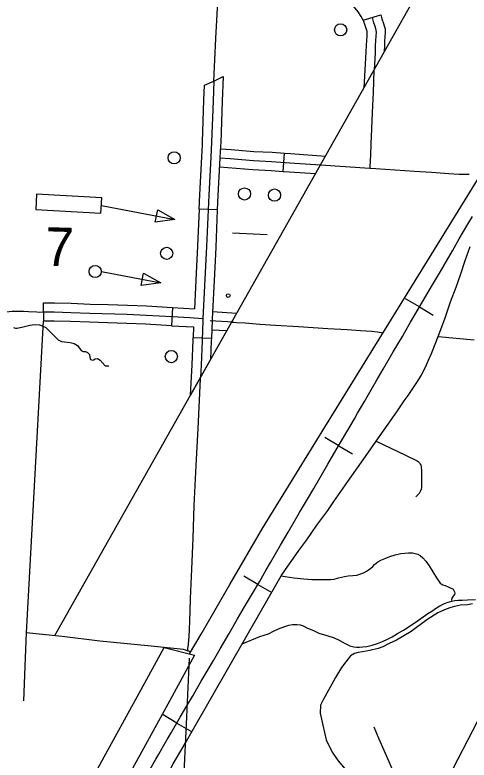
# Model space of a CAD drawing. Extents: x 653372 to 905732, y 627442 to 787275.
# Drawn here: x 693304 to 697040, y 749166 to 755293 of the extents above; entities that cross this region are included whole.
import ezdxf

# ---------------------------------------------------------------- set-up
doc = ezdxf.new("R2010")
doc.units = 0
for name, color, linetype in [('15', 7, 'Continuous'), ('31', 7, 'Continuous'), ('32', 7, 'Continuous'), ('33', 7, 'Continuous'), ('35', 7, 'Continuous'), ('40', 7, 'Continuous'), ('45', 7, 'Continuous'), ('46', 7, 'Continuous'), ('56', 7, 'Continuous'), ('57', 7, 'Continuous'), ('6', 7, 'Continuous'), ('63', 7, 'Continuous')]:
    doc.layers.add(name, color=color, linetype=linetype)

msp = doc.modelspace()

# ---------------------------------------------------------------- linework, layer by layer
at = {"layer": '15'}
for points in [[(694740.6, 750040.6), (694835.2, 750202.4), (695073.2, 750608.7), (695344.3, 751076.3), (695832.2, 751869.1), (697303.4, 754253.1)], [(693255.3, 747643), (693125.3, 747883.4), (693577.6, 748439.7), (693782.1, 748722.2), (693910, 748955), (694023, 749162.6), (694325.7, 749716.7), (694531.2, 750092.3), (694781, 750027.9)], [(694781, 750027.9), (694545.1, 749596.7), (694242.5, 749042.9), (694129.3, 748835), (693993.7, 748588.1), (693776.2, 748287.7), (693255.3, 747643)]]:
    msp.add_lwpolyline(points, dxfattribs=at)
at = {"layer": '31'}
for p, q in [((694969.2, 753689.8), (694819.4, 753696.4)), ((694819.4, 753696.4), (694819.4, 753696.4)), ((693540.9, 752775.5), (693540.1, 752925.5)), ((693540.1, 752925.5), (693540.1, 752925.5)), ((694600, 752887.4), (694591.4, 752737.6)), ((694770.5, 752641), (694920.4, 752635.4))]:
    msp.add_line(p, q, dxfattribs=at)
for points in [[(694941.2, 754748), (694957.2, 755099.5), (694985.9, 755652), (694986.9, 755707.5), (694990.1, 755812.4)], [(694941.2, 754748), (694933.9, 754587.5), (694922.4, 754246.4), (694915.8, 754122.6), (694899.5, 753811.1), (694880.9, 753387.8), (694851.3, 752796.2), (694850.8, 752782.5), (694844.6, 752615.9), (694836.5, 752412.3), (694831.2, 752313.7)], [(694846.1, 754224.3), (694847.4, 754249.6), (694859, 754590.5), (694864.6, 754714.4), (694941.2, 754748), (695018.1, 754787)], [(695018.1, 754787), (695008.9, 754584.5), (694997.3, 754243.1), (694995.9, 754216.4)], [(694819.4, 753696.4), (694824.6, 753814.7), (694840.9, 754126.6), (694846.1, 754224.3)], [(694995.9, 754216.4), (694990.7, 754118.7), (694974.4, 753807.4), (694969.2, 753689.8)], [(694819.4, 753696.4), (694805.9, 753391.3), (694794.9, 753169.4)], [(694969.2, 753689.8), (694955.8, 753384.3), (694944.7, 753161.9)], [(696786.7, 752647.6), (696839.7, 752792.8), (696887.2, 752932.4), (696934.1, 753054.5), (696968.6, 753154.7), (697009.1, 753272.9), (697048.8, 753387.6)], [(694794.9, 753169.4), (694780.3, 752877.5)], [(694944.7, 753161.9), (694926.2, 752792.8), (694925.7, 752779.7), (694920.4, 752635.4)], [(693540.1, 752925.5), (693556.4, 752925.6), (693629.4, 752926), (693768, 752921.8), (693922.2, 752915.7), (694070.5, 752911.3)], [(694070.5, 752911.3), (694229.2, 752906.5), (694387.6, 752899.6), (694600, 752887.4)], [(693540.5, 752850.5), (693556.8, 752850.6), (693628.4, 752851), (693765.4, 752846.8), (693919.6, 752840.8), (694226.4, 752831.6), (694383.8, 752824.6), (694596.6, 752812.5), (694742.1, 752804.5), (694851.3, 752796.2)], [(694600, 752887.4), (694600.9, 752887.3), (694780.3, 752877.5)], [(694066, 752761.3), (693917, 752765.8), (693762.8, 752771.9), (693627.5, 752776), (693557.2, 752775.6), (693540.9, 752775.5)], [(694591.4, 752737.6), (694380.1, 752749.7), (694223.6, 752756.6), (694066, 752761.3)], [(694591.4, 752737.6), (694592.4, 752737.6), (694773.7, 752727.6)], [(694773.7, 752727.6), (694770.5, 752641)], [(694748.3, 752166.9), (694761.6, 752415.8), (694769.6, 752618.8), (694770.5, 752641)], [(694920.4, 752635.4), (694919.5, 752613), (694913.4, 752459.2), (694748.3, 752166.9)], [(696274.7, 751788.2), (696373.6, 751927.5), (696450.9, 752038.3), (696505.1, 752121.2), (696537.8, 752164.4), (696583, 752230), (696610.1, 752271.1), (696629.1, 752299.9), (696648.2, 752330.7), (696663.7, 752361), (696681.4, 752395.9), (696706.8, 752453.1), (696731.5, 752508.2), (696761.1, 752586.9), (696786.7, 752647.6)], [(694725.8, 750070.8), (694727.2, 750081.2), (694731.2, 750116.8), (694736.5, 750184.4), (694739.7, 750236.9), (694743, 750314.5), (694745.1, 750394.4), (694749.1, 750494.3), (694758.6, 750735.9), (694769.9, 750991.2), (694779.9, 751259.3), (694794.1, 751588.9), (694810.4, 751892), (694830.5, 752299.5), (694831.2, 752313.7)], [(694705.6, 749303.5), (694773.5, 749422.8), (695493.5, 750682.4), (695549.6, 750760.3), (695594.8, 750826.6), (695640.7, 750888.8), (695705.4, 750977.6), (695787.2, 751098.7), (695877.4, 751217.5), (695927.1, 751292.8), (696044, 751456.4), (696187.7, 751662.9), (696274.7, 751788.2)], [(695173.6, 750122.7), (695319.3, 750181.6), (695391.5, 750204.4), (695432.4, 750226.3), (695473.7, 750246.7), (695525.6, 750264.1), (695557.8, 750274.5), (695587.8, 750280.1), (695622.5, 750282.3), (695651.6, 750277.7), (695676.2, 750269.3), (695711.2, 750252), (695759.3, 750232.1), (695804.7, 750210.7), (695870.2, 750191.5), (695930.2, 750172.3), (695972.4, 750153.2), (695996.3, 750139.5), (696020.1, 750125.8), (696044.1, 750113.7), (696060.6, 750106.1), (696091.7, 750097.1), (696113.3, 750093.7), (696137.7, 750094.1), (696163.2, 750096.6), (696198.5, 750101.5), (696243.7, 750110.9), (696287.7, 750125.9), (696328.2, 750142), (696368.8, 750159.7), (696406.2, 750179.7), (696450.8, 750206), (696502.1, 750235.8), (696546.8, 750264.8), (696624.7, 750317.7), (696701, 750372.2), (696732.5, 750391.3), (696771.7, 750418.8), (696800.9, 750435.8), (696837.1, 750452.6), (696868.4, 750465.2), (696898.4, 750473.5), (696922.3, 750477.6), (696951.1, 750481.6), (696984.4, 750482.2), (697027.3, 750484.2), (697093.4, 750486)]]:
    msp.add_lwpolyline(points, dxfattribs=at)
at = {"layer": '32'}
msp.add_line((695512, 754006.1), (695522.7, 754155.8), dxfattribs=at)
for points in [[(694995.6, 754192), (695081.9, 754185.6), (695270.9, 754170.3), (695420.6, 754163.1), (695522.7, 754155.8)], [(695522.7, 754155.8), (695571.4, 754152.3), (695858.2, 754132.2)], [(694990.7, 754117.1), (695076.1, 754110.9), (695266, 754095.5), (695416.1, 754088.2), (695566.1, 754077.5), (695817.4, 754059.9)], [(694986.8, 754042.9), (695261.2, 754020.6), (695411.6, 754013.3), (695512, 754006.1)], [(695512, 754006.1), (695560.8, 754002.6), (695776.6, 753987.5)], [(695817.3, 754059.6), (696224.4, 754033.4), (696272.5, 754029.2), (696592.4, 754008.5), (696730.1, 754000.3), (696873.8, 753989.7), (696957.4, 753983.7), (697021.1, 753983.2), (697040.5, 753982.6)], [(695128, 752839.2), (694929.2, 752851.9)], [(695100.1, 752765.8), (694909.8, 752778)], [(695087.1, 752766.7), (695127.4, 752764.1), (695198.7, 752761.4), (695319.9, 752750.6), (695447, 752743.2), (695637.9, 752729.7), (695879.7, 752715.9), (696038.6, 752706.9), (696146.2, 752698.3), (696240.6, 752691.3), (696285.7, 752687.6), (696331.2, 752677.7)], [(695046.1, 752694.1), (694922.8, 752702)], [(696786.7, 752647.6), (697083.1, 752622.2)], [(695493.5, 750682.4), (695528.6, 750676.2), (695597.6, 750665.5), (695681.2, 750657.6), (695746.6, 750651.3), (695780.1, 750650.3), (695821.8, 750650.1), (695872.1, 750650.2), (695900.5, 750651.5), (695929.8, 750655), (695966.4, 750663.6), (696016.5, 750675.6), (696045.9, 750680.7), (696083.9, 750685), (696115.9, 750687.8), (696133.4, 750691.1), (696159.1, 750700.1), (696177.7, 750707.6), (696201.4, 750722.1), (696231.9, 750745.5), (696247.4, 750757.5), (696263.3, 750774.4), (696288.3, 750795.3), (696315.3, 750810.7), (696355.3, 750827.4), (696388.2, 750839.9), (696432.4, 750852.7), (696479.3, 750863.7), (696512.4, 750868.7), (696541.7, 750871), (696574.2, 750869.5), (696597.3, 750864.5), (696618.1, 750859), (696636.7, 750848.7), (696659.9, 750829), (696684, 750802.3), (696711, 750763.6), (696773, 750663.7), (696803.1, 750620.6), (696810.5, 750614.4), (696824.3, 750607.5), (696842.5, 750601.5), (696867, 750591.1), (696908.1, 750570.3), (696915.4, 750561.5), (696921, 750551), (696921.8, 750540.1), (696919.8, 750528.8), (696908, 750512.9), (696898.9, 750498.6), (696895.2, 750484.1), (696898.4, 750473.5)]]:
    msp.add_lwpolyline(points, dxfattribs=at)
at = {"layer": '33'}
for points in [[(692906.9, 752853.4), (692973.4, 752852.4), (693013.2, 752851.8), (693094.2, 752849.7), (693156.7, 752849.8), (693211, 752852.9), (693256.5, 752855.5), (693281.3, 752857.1), (693309.6, 752857), (693346.5, 752856.7), (693375.2, 752855.9), (693414.8, 752854.3), (693483.9, 752850.6), (693508.6, 752849.9), (693540.5, 752850.5)], [(694749.5, 750055.9), (694691.9, 750075.8), (694398.3, 750105.9), (694004, 750145.1), (693691.7, 750181.8), (693397.5, 750213.1), (693388.9, 750006.8), (693374.1, 749654.1)], [(694723, 750062.7), (694725.8, 750070.8)], [(693300.2, 747217.8), (693538.5, 747527.5), (693619.8, 747634.1), (693710.8, 747747.8), (693807.8, 747869.9), (693900.6, 747992.3), (693950.9, 748063.4), (694025.6, 748169.8), (694104.2, 748284.2), (694138.4, 748345), (694210.2, 748462.9), (694313, 748628.2), (694349.3, 748688.3), (694397.1, 748770), (694430.5, 748825.4), (694478.5, 748910.6), (694530.8, 748998), (694606.2, 749134.9), (694705.6, 749303.5)]]:
    msp.add_lwpolyline(points, dxfattribs=at)
at = {"layer": '35'}
for points in [[(693291.4, 752722.5), (693310, 752716.2), (693319.4, 752716.8), (693361.4, 752726.2), (693426.6, 752742.8), (693465.7, 752748.7), (693505.5, 752745.8), (693528.3, 752737.1), (693558.9, 752722.9), (693623.4, 752657.1), (693661.3, 752621.4), (693687.5, 752606.4), (693759.9, 752599), (693791.6, 752591.8), (693820.4, 752575.9), (693848.5, 752533.5), (693866.8, 752524.1), (693884.6, 752526.2), (693901.2, 752518.6), (693916.6, 752499.5), (693919.5, 752478.1), (693927, 752460.2), (693944.5, 752454.3), (693950.4, 752457.5), (693964.3, 752464.4), (693984.8, 752467.3), (694006.6, 752455.1), (694047.7, 752407.8), (694077.4, 752406.9)], [(697068.6, 750451.7), (697026.2, 750442), (696968.6, 750439.9), (696920, 750428.9), (696883, 750417.5), (696838.5, 750402.4), (696783.2, 750376), (696693.5, 750318.8), (696563, 750224.6), (696442.6, 750153.4), (696383.3, 750124), (696331.9, 750096.8), (696292.6, 750083.9), (696225.1, 750066.5), (696162.5, 750055.1), (696127.3, 750050), (696098.2, 750041.5), (696065.7, 750023), (696027.7, 749975.1), (695990.5, 749928.7), (695966.8, 749885.2), (695942.3, 749845.5), (695838.8, 749662.3)], [(695838.8, 749662.3), (695818.9, 749617.3), (695815.4, 749552), (695837.4, 749453.2), (695864.9, 749334), (695913.3, 749232.9), (695962.4, 749159.7), (696049.7, 749059), (696107.2, 749004.3), (696153.5, 748938.4), (696238.8, 748822.2), (696278.4, 748741.6), (696306.9, 748653.5), (696330.7, 748564), (696354, 748458.9), (696363.2, 748351.2)]]:
    msp.add_lwpolyline(points, dxfattribs=at)
at = {"layer": '40'}
for p, q in [((696632.1, 752892), (696518.2, 752958.6)), ((696632.1, 752892), (696746.1, 752825.3)), ((695968.1, 751751.2), (695854.6, 751818.5)), ((695968.1, 751751.2), (696081.7, 751683.8)), ((695302.6, 750611.2), (695188.6, 750677.7)), ((695302.6, 750611.2), (695416.6, 750544.8)), ((694636.9, 749471.4), (694523.4, 749538.8)), ((694636.9, 749471.4), (694750.4, 749404))]:
    msp.add_line(p, q, dxfattribs=at)
for points in [[(694416.3, 749091.6), (694464.7, 749174.9), (694486.9, 749216.4), (694515.3, 749265.7), (694556.6, 749336.7), (694589, 749390.8), (694664.6, 749518.1), (694718.3, 749611.5), (694764.7, 749690.5), (694836.8, 749814.5), (694884.5, 749896.2), (694936.9, 749986.2), (694991.8, 750080), (695065.9, 750206.5), (695135.9, 750326.5), (695194, 750425.1), (695250.4, 750521.8), (695315.3, 750633), (695372.2, 750730.9), (695406.3, 750791.8), (695488.4, 750932.2), (695551.3, 751040.2), (695605.3, 751132), (695645.8, 751202.2), (695709.8, 751311.3), (695763.4, 751400.2), (695879.5, 751599.2), (695966.8, 751748.9), (696052, 751892.6), (696097.7, 751972.6), (696123.4, 752017.8), (696179.1, 752114.5), (696234.8, 752210.5), (696277.2, 752282.6), (696333.7, 752380.8), (696416.6, 752522.3), (696491.4, 752648.5), (696510.7, 752683.3), (696558.8, 752766.5), (696657.3, 752934.9), (696730.1, 753060.4), (696771.6, 753127.5), (696804.8, 753183.5), (696835.6, 753235.7), (696903.3, 753351.8), (696958.7, 753451), (696994.4, 753512.6), (697030.3, 753572), (697067.9, 753635.1)], [(695645.8, 751202.2), (695709.8, 751311.3), (695763.4, 751400.2), (695879.5, 751599.2), (695966.8, 751748.9), (696052, 751892.6), (696097.7, 751972.6), (696123.4, 752017.8), (696179.1, 752114.5), (696234.8, 752210.5), (696277.2, 752282.6), (696333.7, 752380.8), (696416.6, 752522.3), (696491.4, 752648.5), (696510.7, 752683.3), (696558.8, 752766.5), (696657.3, 752934.9), (696730.1, 753060.4), (696771.6, 753127.5), (696804.8, 753183.5), (696835.6, 753235.7), (696903.3, 753351.8), (696958.7, 753451), (696994.4, 753512.6), (697030.3, 753572), (697067.9, 753635.1)], [(694416.3, 749091.6), (694464.7, 749174.9), (694486.9, 749216.4), (694515.3, 749265.7), (694556.6, 749336.7), (694589, 749390.8), (694664.6, 749518.1), (694718.3, 749611.5), (694764.7, 749690.5), (694836.8, 749814.5), (694884.5, 749896.2), (694936.9, 749986.2), (694991.8, 750080), (695065.9, 750206.5), (695135.9, 750326.5), (695194, 750425.1), (695250.4, 750521.8), (695315.3, 750633), (695372.2, 750730.9), (695406.3, 750791.8), (695488.4, 750932.2), (695551.3, 751040.2), (695605.3, 751132), (695645.8, 751202.2)]]:
    msp.add_lwpolyline(points, dxfattribs=at)
at = {"layer": '45'}
msp.add_line((696169.8, 755250.5), (696313.8, 755292.6), dxfattribs=at)
for points in [[(696313.8, 755292.6), (696323.3, 755260.1), (696335.4, 755223), (696342.6, 755202.9), (696348.9, 755178.9), (696350.4, 755147.7), (696348.5, 755115.2), (696345.6, 755070.8), (696343.6, 755039.7), (696341.7, 754988.3)], [(696169.8, 755250.5), (696180, 755215.7), (696193.5, 755174.5), (696199.1, 755158.6), (696199.8, 755156), (696200.2, 755148.3), (696198.8, 755124.4), (696196, 755080.6), (696193.8, 755047.4), (696191.5, 754985.5), (696174.8, 754692.6)], [(696241.8, 755271.5), (696251.7, 755237.9), (696264.4, 755198.7), (696270.9, 755180.7), (696274.3, 755167.4), (696275.3, 755148), (696273.7, 755119.8), (696270.8, 755075.7), (696268.7, 755043.6), (696266.4, 754982), (696258.4, 754840.6)], [(696257.7, 754839.4), (696251.2, 754655.3), (696243.9, 754490.8), (696238.7, 754355.3), (696232.3, 754232), (696228.8, 754141.4), (696224.8, 754047.6), (696224.4, 754033.4)], [(696274.7, 751788.2), (696516, 751673.5), (696614, 751625.7), (696621.8, 751620), (696632.5, 751609.8), (696638.6, 751599.6), (696642.3, 751590.6), (696645.5, 751581), (696646.6, 751571.2), (696648.5, 751550.2), (696649.5, 751519.3), (696650.2, 751475.5), (696649.7, 751423.9), (696648.6, 751405), (696647.3, 751393.6), (696640.9, 751379.8), (696629.3, 751358.3), (696603.5, 751329.4)]]:
    msp.add_lwpolyline(points, dxfattribs=at)
at = {"layer": '46'}
for points in [[(696169.8, 755250.5), (696152.9, 755280.8), (696128.3, 755317.5), (696102, 755347.6), (696060.4, 755399.5), (696031.9, 755438.6), (696009.2, 755487.6), (695994.7, 755534.9), (695987.7, 755584.3), (695985.8, 755616.4), (695982, 755632.2), (695975.4, 755658.9), (695964, 755694.3), (695953.5, 755719.6), (695948.5, 755730.2), (695939.7, 755742), (695917.5, 755764.5), (695908, 755773.5), (695903.2, 755776.4), (695897.3, 755778.6), (695875.3, 755785), (695842.8, 755795.2)], [(696257.2, 749441.2), (696297.4, 749342.2), (696379.4, 749155.4), (696443.2, 749006.7), (696477, 748922.7), (696497.1, 748869.7), (696510.6, 748829.5), (696527.8, 748756.9), (696549.1, 748672), (696568.1, 748585), (696576.3, 748516.5), (696583.1, 748466.8)]]:
    msp.add_lwpolyline(points, dxfattribs=at)
at = {"layer": '56'}
for p, q in [((694343.9, 753068.2), (694362.9, 753168.4)), ((694362.9, 753168.4), (694503.7, 753089.9)), ((694503.7, 753089.9), (694343.9, 753068.2))]:
    msp.add_line(p, q, dxfattribs=at)
msp.add_lwpolyline([(694016.8, 753182), (694503.7, 753089.9)], dxfattribs=at)
for centre, radius in [((695983.6, 755169.5), 50), ((694613.8, 754117.1), 50), ((695193.1, 753820.7), 50), ((695439.9, 753811.5), 50), ((694552.7, 753332.5), 50), ((693964.6, 753183.5), 50), ((695059, 752985.1), 15), ((694591.2, 752483.6), 50)]:
    msp.add_circle(centre, radius, dxfattribs=at)
at = {"layer": '57'}
for p, q in [((693482.2, 753818.2), (693475.4, 753693.3)), ((694018.9, 753788.8), (693482.2, 753818.2)), ((694012.1, 753664), (694018.9, 753788.8)), ((693475.4, 753693.3), (694012.1, 753664)), ((694459.3, 753588.9), (694478.6, 753689.1)), ((694478.6, 753689.1), (694619.2, 753610)), ((694619.2, 753610), (694459.3, 753588.9))]:
    msp.add_line(p, q, dxfattribs=at)
for points in [[(694015.5, 753726.4), (694619.2, 753610)], [(695042.1, 753508.4), (695042.3, 753508.4)], [(695094, 753501.2), (695379.6, 753486.3)]]:
    msp.add_lwpolyline(points, dxfattribs=at)
at = {"layer": '6'}
for points in [[(693536.4, 752775.5), (693397.5, 750213.1)], [(694738.9, 750004.8), (694713.1, 749460.8), (694559.9, 746262), (693308.7, 746254.9)]]:
    msp.add_lwpolyline(points, dxfattribs=at)
at = {"layer": '63'}
for p, q in [((696691.9, 755608.4), (693630.8, 750188.2)), ((699379, 753888.6), (696650.2, 748597.1))]:
    msp.add_line(p, q, dxfattribs=at)

# ---------------------------------------------------------------- texts
at = {"layer": '57'}
msp.add_text('7', height=316.8, rotation=358.28003, dxfattribs=at).set_placement((693548, 753231.6))

doc.saveas('drawing.dxf')
